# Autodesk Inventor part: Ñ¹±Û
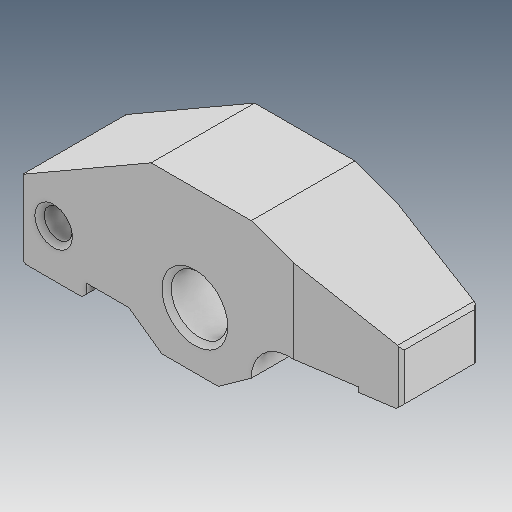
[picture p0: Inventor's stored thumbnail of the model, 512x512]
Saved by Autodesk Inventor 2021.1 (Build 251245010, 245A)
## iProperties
Created: 2014-12
Part Number: Ñ¹±Û
Material: Ogólny
Document SubType Name: Modeling
Designer: user
Density: 1 g/cm^3
Appearance: Domyślna
Author: user
Revision Number: ÈÎºÎ
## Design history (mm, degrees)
feature "ÊäÈë1"
node "Bryła1"
